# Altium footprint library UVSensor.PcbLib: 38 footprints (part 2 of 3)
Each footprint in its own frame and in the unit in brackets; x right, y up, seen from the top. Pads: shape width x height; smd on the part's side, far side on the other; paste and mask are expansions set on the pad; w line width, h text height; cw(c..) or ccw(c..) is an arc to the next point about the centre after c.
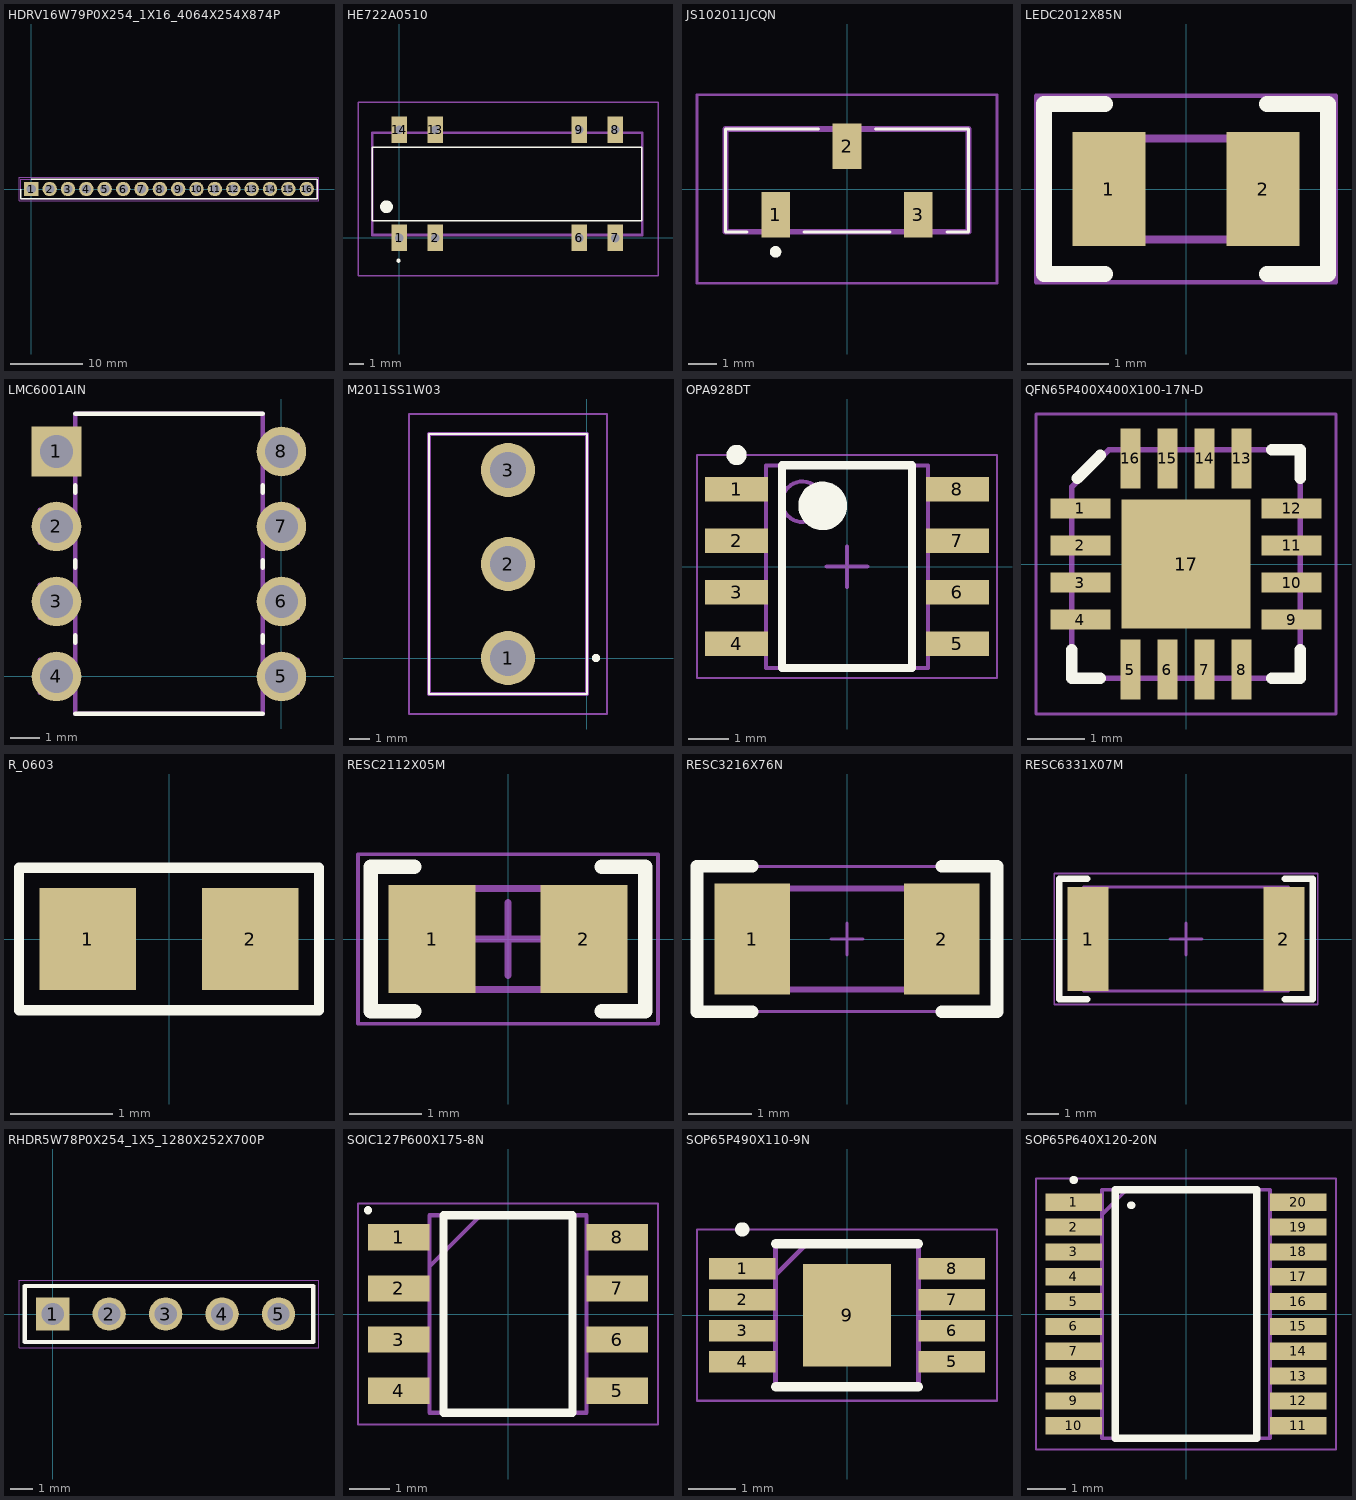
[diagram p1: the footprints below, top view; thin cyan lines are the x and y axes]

## HDRV16W79P0X254_1X16_4064X254X874P [mm]
pads (16):
  rect 2x2 hole 1.3: 1(0,0)
  round 2 hole 1.3: 2(2.54,0) 3(5.08,0) 4(7.62,0) 5(10.16,0) 6(12.7,0) 7(15.24,0) 8(17.78,0) 9(20.32,0) 10(22.86,0) 11(25.4,0) 12(27.94,0) 13(30.48,0) 14(33.02,0) 15(35.56,0) 16(38.1,0)
Top Overlay:
  lines w0.2: -1.445,0 -1.445,-1.345 39.545,-1.345 39.545,1.345 0,1.345
Mechanical 13:
  lines w0.1: -1.445,-1.345 -1.445,1.345 39.545,1.345 39.545,-1.345 -1.445,-1.345
  text ".Designator" at -1.345,1.612 h0.5
Mechanical 15:
  lines w0.05: -1.695,-1.595 -1.695,1.595 39.795,1.595 39.795,-1.595 -1.695,-1.595

## HE722A0510 [mm]
pads (8):
  rect 1.118x1.864 hole 0.61: 1(0,0) 2(2.54,0) 6(12.7,0) 7(15.24,0) 8(15.24,7.62) 9(12.7,7.62) 13(2.54,7.62) 14(0,7.62)
Top Overlay:
  lines w0.1: -1.9,1.2 -1.9,6.4 ; -1.9,1.2 -1.9,6.4 ; -1.9,1.2 17.1,1.2 17.1,6.4 -1.9,6.4
  lines w0.2: -0.1,-1.6 ccw(c-0.05,-1.6) 0,-1.6 ; -0.1,-1.6 cw(c-0.05,-1.6) 0,-1.6 ; -0.1,-1.6 ccw(c-0.05,-1.6) 0,-1.6
  lines w0.5: -1.1,2.2 ccw(c-0.9,2.2) -0.7,2.2 ccw(c-0.9,2.2) -1.1,2.2
Mechanical 13:
  lines w0.2: -1.905,0.2 -1.905,7.42 17.145,7.42 17.145,0.2 -1.905,0.2
  text ".Designator" at 3.2,9.176 h2
Mechanical 15:
  lines w0.1: -2.905,-2.65 -2.905,9.552 18.25,9.552 18.25,-2.65 -2.905,-2.65
3D body "HE722A0510.stp": height 6.75, standoff -1.75, extent -1.925,-1.085 17.125,8.685

## JS102011JCQN [mm]
pads (3):
  rect 1x1.6 smd: 1(-2.5,-0.9) 2(0,1.5) 3(2.5,-0.9)
Top Overlay:
  lines w0.1: -3.5,-1.5 -4.25,-1.5 -4.25,2.1 -1,2.1 ; -1.5,-1.5 1.5,-1.5 ; 1,2.1 4.25,2.1 4.25,-1.5 3.5,-1.5
  lines w0.2: -2.6,-2.2 cw(c-2.5,-2.2) -2.4,-2.2 cw(c-2.5,-2.2) -2.6,-2.2
Mechanical 13:
  lines w0.2: -4.25,-1.5 4.25,-1.5 4.25,2.1 -4.25,2.1 -4.25,-1.5
  text ".Designator" at 1.727,1.281 h0.76
Mechanical 15:
  lines w0.1: -5.25,-3.3 5.25,-3.3 5.25,3.3 -5.25,3.3 -5.25,-3.3
3D body "JS102011JCQN.stp": height 5.65, standoff 0, extent -4.25,-1.75 4.25,2.35

## LEDC2012X85N [mm]
pads (2):
  rect 0.9x1.4 smd: 1(-0.95,0) 2(0.95,0)
Top Overlay:
  lines w0.2: -1,-1.05 -1.75,-1.05 -1.75,1.05 -1,1.05 ; 1,-1.05 1.75,-1.05 1.75,1.05 1,1.05
Mechanical 13:
  lines w0.1: -1,0.208 -0.583,0.625 ; -1,-0.625 -1,0.625 1,0.625 1,-0.625 -1,-0.625
  text ".Designator" at -1.653,1.308 h0.5
Mechanical 15:
  lines w0.05: -1.85,-1.15 -1.85,1.15 1.85,1.15 1.85,-1.15 -1.85,-1.15
3D body "APT2012LZGCK.stp": height 0.75, standoff 0, extent -1.03,-0.625 0.97,0.625

## LMC6001AIN [mil]
pads (8):
  rect 66x66 hole 44: 1(-300,300)
  round 66 hole 44: 2(-300,200) 3(-300,100) 4(-300,0) 5(0,0) 6(0,100) 7(0,200) 8(0,300)
Top Overlay:
  lines w6: -275,-50 -25,-50 ; -275,45 -275,55 ; -275,145 -275,155 ; -275,245 -275,255 ; -275,350 -162,350 -138,350 -25,350 ; -25,45 -25,55 ; -25,145 -25,155 ; -25,245 -25,255
Mechanical 13:
  lines w6: -322,-22 -275,-22 -275,22 -322,22 -322,-22 ; -322,78 -275,78 -275,122 -322,122 -322,78 ; -322,178 -275,178 -275,222 -322,222 -322,178 ; -322,278 -275,278 -275,322 -322,322 -322,278 ; -275,-50 -275,350 -162,350 -138,350 -25,350 -25,-50 -275,-50 ; -25,-22 22,-22 22,22 -25,22 -25,-22 ; -25,78 22,78 22,122 -25,122 -25,78 ; -25,178 22,178 22,222 -25,222 -25,178 ; -25,278 22,278 22,322 -25,322 -25,278
  text ".Designator" at -246.97,314.21 h30
3D body "LMC6001AIN.stp": height 165.72, standoff -132.54, extent -311.49,-32.5 11.49,332.5

## M2011SS1W03 [mm]
pads (3):
  round 2.7 hole 1.8: 1(-3.95,0) 2(-3.95,4.7) 3(-3.95,9.4)
Top Overlay:
  lines w0.1: -7.9,-1.8 -7.9,11.2 0,11.2 0,-1.8 -7.9,-1.8
  lines w0.2: 0.45,-0.1 ccw(c0.45,0) 0.45,0.1 ccw(c0.45,0) 0.45,-0.1
Mechanical 13:
  lines w0.2: -7.9,-1.8 -7.9,11.2 0,11.2 0,-1.8 -7.9,-1.8
  text ".Designator" at -8.385,11.785 h1
Mechanical 15:
  lines w0.1: -8.9,-2.8 -8.9,12.2 1,12.2 1,-2.8 -8.9,-2.8
3D body "M2011SS1W03.stp": height 28.77, standoff -6.62, extent -9.943,-1.802 2.043,11.202

## OPA928DT [mm] "SOIC, 8-Leads, Body 4,91x3,90mm, Pitch 1,27mm, IPC Medium Density"
height 1.75
pads (8):
  rect 1.55x0.6 smd: 1(-2.725,1.905) 2(-2.725,0.635) 3(-2.725,-0.635) 4(-2.725,-1.905) 5(2.725,-1.905) 6(2.725,-0.635) 7(2.725,0.635) 8(2.725,1.905)
Top Overlay:
  circle w0.6: c-0.6,1.5 r0.3
  circle w0.25: c-2.725,2.755 r0.125
  lines w0.2: -1.6,-2.5 1.6,-2.5 1.6,2.5 -1.6,2.5 -1.6,-2.5
Mechanical 13:
  circle w0.1: c-1.1,1.6 r0.5
  lines w0.1: -2,-2.5 2,-2.5 2,2.5 -2,2.5 -2,-2.5
  text ".Designator" at -1.9,2.767 h0.5
Mechanical 15:
  lines w0.05: -3.7,-2.75 3.7,-2.75 3.7,2.75 -3.7,2.75 -3.7,-2.75
  lines w0.1: -0.5,0 0.5,0 ; 0,-0.5 0,0.5
3D body "SOIC127P600X175-8N.step": height 1.75, standoff 0, extent -2.997,-2.5 2.997,2.5

## QFN65P400X400X100-17N-D [mm]
pads (17):
  rect 1.05x0.35 smd: 1(-1.85,0.975) 2(-1.85,0.325) 3(-1.85,-0.325) 4(-1.85,-0.975) 9(1.85,-0.975) 10(1.85,-0.325) 11(1.85,0.325) 12(1.85,0.975)
  rect 0.35x1.05 smd: 5(-0.975,-1.85) 6(-0.325,-1.85) 7(0.325,-1.85) 8(0.975,-1.85) 13(0.975,1.85) 14(0.325,1.85) 15(-0.325,1.85) 16(-0.975,1.85)
  rect 2.26x2.26 smd: 17(0,0)
Top Overlay:
  lines w0.2: -2,-1.5 -2,-2 -1.5,-2 ; -1.9,1.5 -1.5,1.9 ; 1.5,-2 2,-2 2,-1.5 ; 1.5,2 2,2 2,1.5
Mechanical 13:
  lines w0.1: -2,1.35 -1.35,2 ; -2,1.35 -2,-2 2,-2 2,2 -1.35,2 ; -2,1.35 -1.35,2
  text ".Designator" at 0.127,0.381 h0.76
Mechanical 15:
  lines w0.05: -2.625,-2.625 2.625,-2.625 2.625,2.625 -2.625,2.625 -2.625,-2.625
3D body "LOG114AIRGVT.stp": height 1, standoff 0, extent -2,-2 2,2

## R_0603 [mm]
pads (2):
  rect 0.95x1 smd: 1(-0.8,0) 2(0.8,0)
Top Overlay:
  lines w0.1: -1.475,-0.7 -1.475,0.7 1.475,0.7 1.475,-0.7 -1.475,-0.7
Mechanical 13:
  text ".Designator" at -0.023,0.481 h0.76
3D body "Resistor 0603.step": height 0.5, standoff 0, extent -1.05,-0.4 1.05,0.4

## RESC2112X05M [mm] "Resistor, 0805 (2012 metric), 2.05x1.25x0.5mm, Vishay"
height 0.5
pads (2):
  rect 1.2x1.5 smd: 1(-1.05,0) 2(1.05,0)
Top Overlay:
  lines w0.2: -1.3,-1 -1.9,-1 -1.9,1 -1.3,1 ; 1.3,-1 1.9,-1 1.9,1 1.3,1
Mechanical 13:
  lines w0.1: -1.1,-0.7 1.1,-0.7 1.1,0.7 -1.1,0.7 -1.1,-0.7
  text ".Designator" at -2.825,1.45 h1.52
Mechanical 15:
  lines w0.05: -2.075,-1.175 2.075,-1.175 2.075,1.175 -2.075,1.175 -2.075,-1.175
  lines w0.1: -0.5,0 0.5,0 ; 0,-0.5 0,0.5
3D body "RESC2112X05M.step": height 0.5, standoff 0, extent -1.1,-0.7 1.1,0.7

## RESC3216X76N [mm]
pads (2):
  rect 1.2x1.75 smd: 1(-1.5,0) 2(1.5,0)
Top Overlay:
  lines w0.2: -1.5,-1.15 -2.375,-1.15 -2.375,1.15 -1.5,1.15 ; 1.5,-1.15 2.375,-1.15 2.375,1.15 1.5,1.15
Mechanical 13:
  lines w0.1: -1.6,-0.8 1.6,-0.8 1.6,0.8 -1.6,0.8 -1.6,-0.8
  text ".Designator" at -2.3,1.467 h0.5
Mechanical 15:
  lines w0.05: -0.25,0 0.25,0 ; 0,-0.25 0,0.25 ; -2.35,-1.15 2.35,-1.15 2.35,1.15 -2.35,1.15 -2.35,-1.15
3D body "HVCB1206BDE100M.stp": height 0.76, standoff 0, extent -1.6,-0.8 1.6,0.8

## RESC6331X07M [mm] "Resistor, 2512 (6332 metric), 6.3x3.2x0.7mm, Vishay"
height 0.7
pads (2):
  rect 1.3x3.3 smd: 1(-3.1,0) 2(3.1,0)
Top Overlay:
  lines w0.2: -3.125,-1.905 -4.014,-1.905 -4.014,1.905 -3.125,1.905 ; 3.125,-1.905 4.014,-1.905 4.014,1.905 3.125,1.905
Mechanical 13:
  lines w0.1: -3.25,-1.65 -3.25,1.65 3.25,1.65 3.25,-1.65 -3.25,-1.65
  text ".Designator" at -2.794,-0.381 h1.52
Mechanical 15:
  lines w0.05: -4.175,-2.075 -4.175,2.075 4.175,2.075 4.175,-2.075 -4.175,-2.075
  lines w0.1: -0.5,0 0.5,0 ; 0,-0.5 0,0.5
3D body "RESC6331X07M.step": height 0.7, standoff 0, extent -3.25,-1.65 3.25,1.65

## RHDR5W78P0X254_1X5_1280X252X700P [mm]
pads (5):
  rect 1.5x1.5 hole 1: 1(0,0)
  round 1.5 hole 1: 2(2.54,0) 3(5.08,0) 4(7.62,0) 5(10.16,0)
Top Overlay:
  lines w0.2: -1.27,-1.26 11.73,-1.26 11.73,1.26 -1.27,1.26 -1.27,-1.25
Mechanical 13:
  lines w0.1: -1.27,-1.26 -1.27,1.26 11.73,1.26 11.73,-1.26 -1.27,-1.26
  text ".Designator" at 3.502,0.506 h0.76
Mechanical 15:
  lines w0.05: -1.52,-1.51 -1.52,1.51 11.98,1.51 11.98,-1.51 -1.52,-1.51
3D body "215297-5.stp": height 7.02, standoff -2.98, extent -1.25,-1.26 11.45,1.26

## SOIC127P600X175-8N [mm]
pads (8):
  rect 1.528x0.65 smd: 1(-2.711,1.905) 2(-2.711,0.635) 3(-2.711,-0.635) 4(-2.711,-1.905) 5(2.711,-1.905) 6(2.711,-0.635) 7(2.711,0.635) 8(2.711,1.905)
Top Overlay:
  lines w0.2: -3.475,2.575 -3.475,2.58 ; -1.598,-2.452 1.598,-2.452 1.598,2.452 -1.598,2.452 -1.598,-2.452
Mechanical 13:
  lines w0.1: -1.948,1.182 -0.678,2.452 ; -1.948,-2.452 1.948,-2.452 1.948,2.452 -1.948,2.452 -1.948,-2.452
  text ".Designator" at -1.023,1.481 h0.76
Mechanical 15:
  lines w0.05: -3.725,-2.75 3.725,-2.75 3.725,2.75 -3.725,2.75 -3.725,-2.75
3D body "LM79L05ACMX_NOPB.stp": height 1.63, standoff 0, extent -3.011,-2.451 3.011,2.451

## SOP65P490X110-9N [mm]
pads (9):
  rect 1.4x0.45 smd: 1(-2.2,0.975) 2(-2.2,0.325) 3(-2.2,-0.325) 4(-2.2,-0.975) 5(2.2,-0.975) 6(2.2,-0.325) 7(2.2,0.325) 8(2.2,0.975)
  rect 1.846x2.15 smd: 9(0,0)
Top Overlay:
  lines w0.2: -1.5,-1.5 1.5,-1.5 ; -1.5,1.5 1.5,1.5 ; -2.25,1.8 ccw(c-2.2,1.8) -2.15,1.8 ; -2.25,1.8 cw(c-2.2,1.8) -2.15,1.8 ; -2.25,1.8 ccw(c-2.2,1.8) -2.15,1.8
Mechanical 13:
  lines w0.1: -1.5,0.85 -0.85,1.5 ; -1.5,-1.5 -1.5,1.5 1.5,1.5 1.5,-1.5 -1.5,-1.5
  text ".Designator" at -2.2,1.988 h1
Mechanical 15:
  lines w0.05: -3.15,-1.8 -3.15,1.8 3.15,1.8 3.15,-1.8 -3.15,-1.8
3D body "TPS7B8150DGNR.stp": height 1.1, standoff 0, extent -2.45,-1.5 2.45,1.5

## SOP65P640X120-20N [mm]
pads (20):
  rect 1.475x0.45 smd: 1(-2.938,2.925) 2(-2.938,2.275) 3(-2.938,1.625) 4(-2.938,0.975) 5(-2.938,0.325) 6(-2.938,-0.325) 7(-2.938,-0.975) 8(-2.938,-1.625) 9(-2.938,-2.275) 10(-2.938,-2.925) 11(2.938,-2.925) 12(2.938,-2.275) 13(2.938,-1.625) 14(2.938,-0.975) 15(2.938,-0.325) 16(2.938,0.325) 17(2.938,0.975) 18(2.938,1.625) 19(2.938,2.275) 20(2.938,2.925)
Top Overlay:
  lines w0.2: -2.946,3.505 -2.921,3.505 ; -1.448,2.845 -1.422,2.845 ; -1.85,-3.25 -1.85,3.25 1.85,3.25 1.85,-3.25 -1.85,-3.25
Mechanical 13:
  lines w0.1: -2.2,2.6 -1.55,3.25 ; -2.2,-3.25 -2.2,3.25 2.2,3.25 2.2,-3.25 -2.2,-3.25
  text ".Designator" at -1.729,3.518 h0.5
Mechanical 15:
  lines w0.05: -3.925,-3.55 -3.925,3.55 3.925,3.55 3.925,-3.55 -3.925,-3.55
3D body "ADS131M03IPWR.stp": height 1.13, standoff 0, extent -3.2,-3.25 3.2,3.25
